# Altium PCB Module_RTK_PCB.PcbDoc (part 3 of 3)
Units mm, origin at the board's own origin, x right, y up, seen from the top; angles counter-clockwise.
Board outline 99.98 x 60 mm, 4 copper layers (Top Layer, gnd, vcc, Bottom Layer), stack 1.536 mm thick; 168 components, 121 nets, 582 pads, 666 vias.
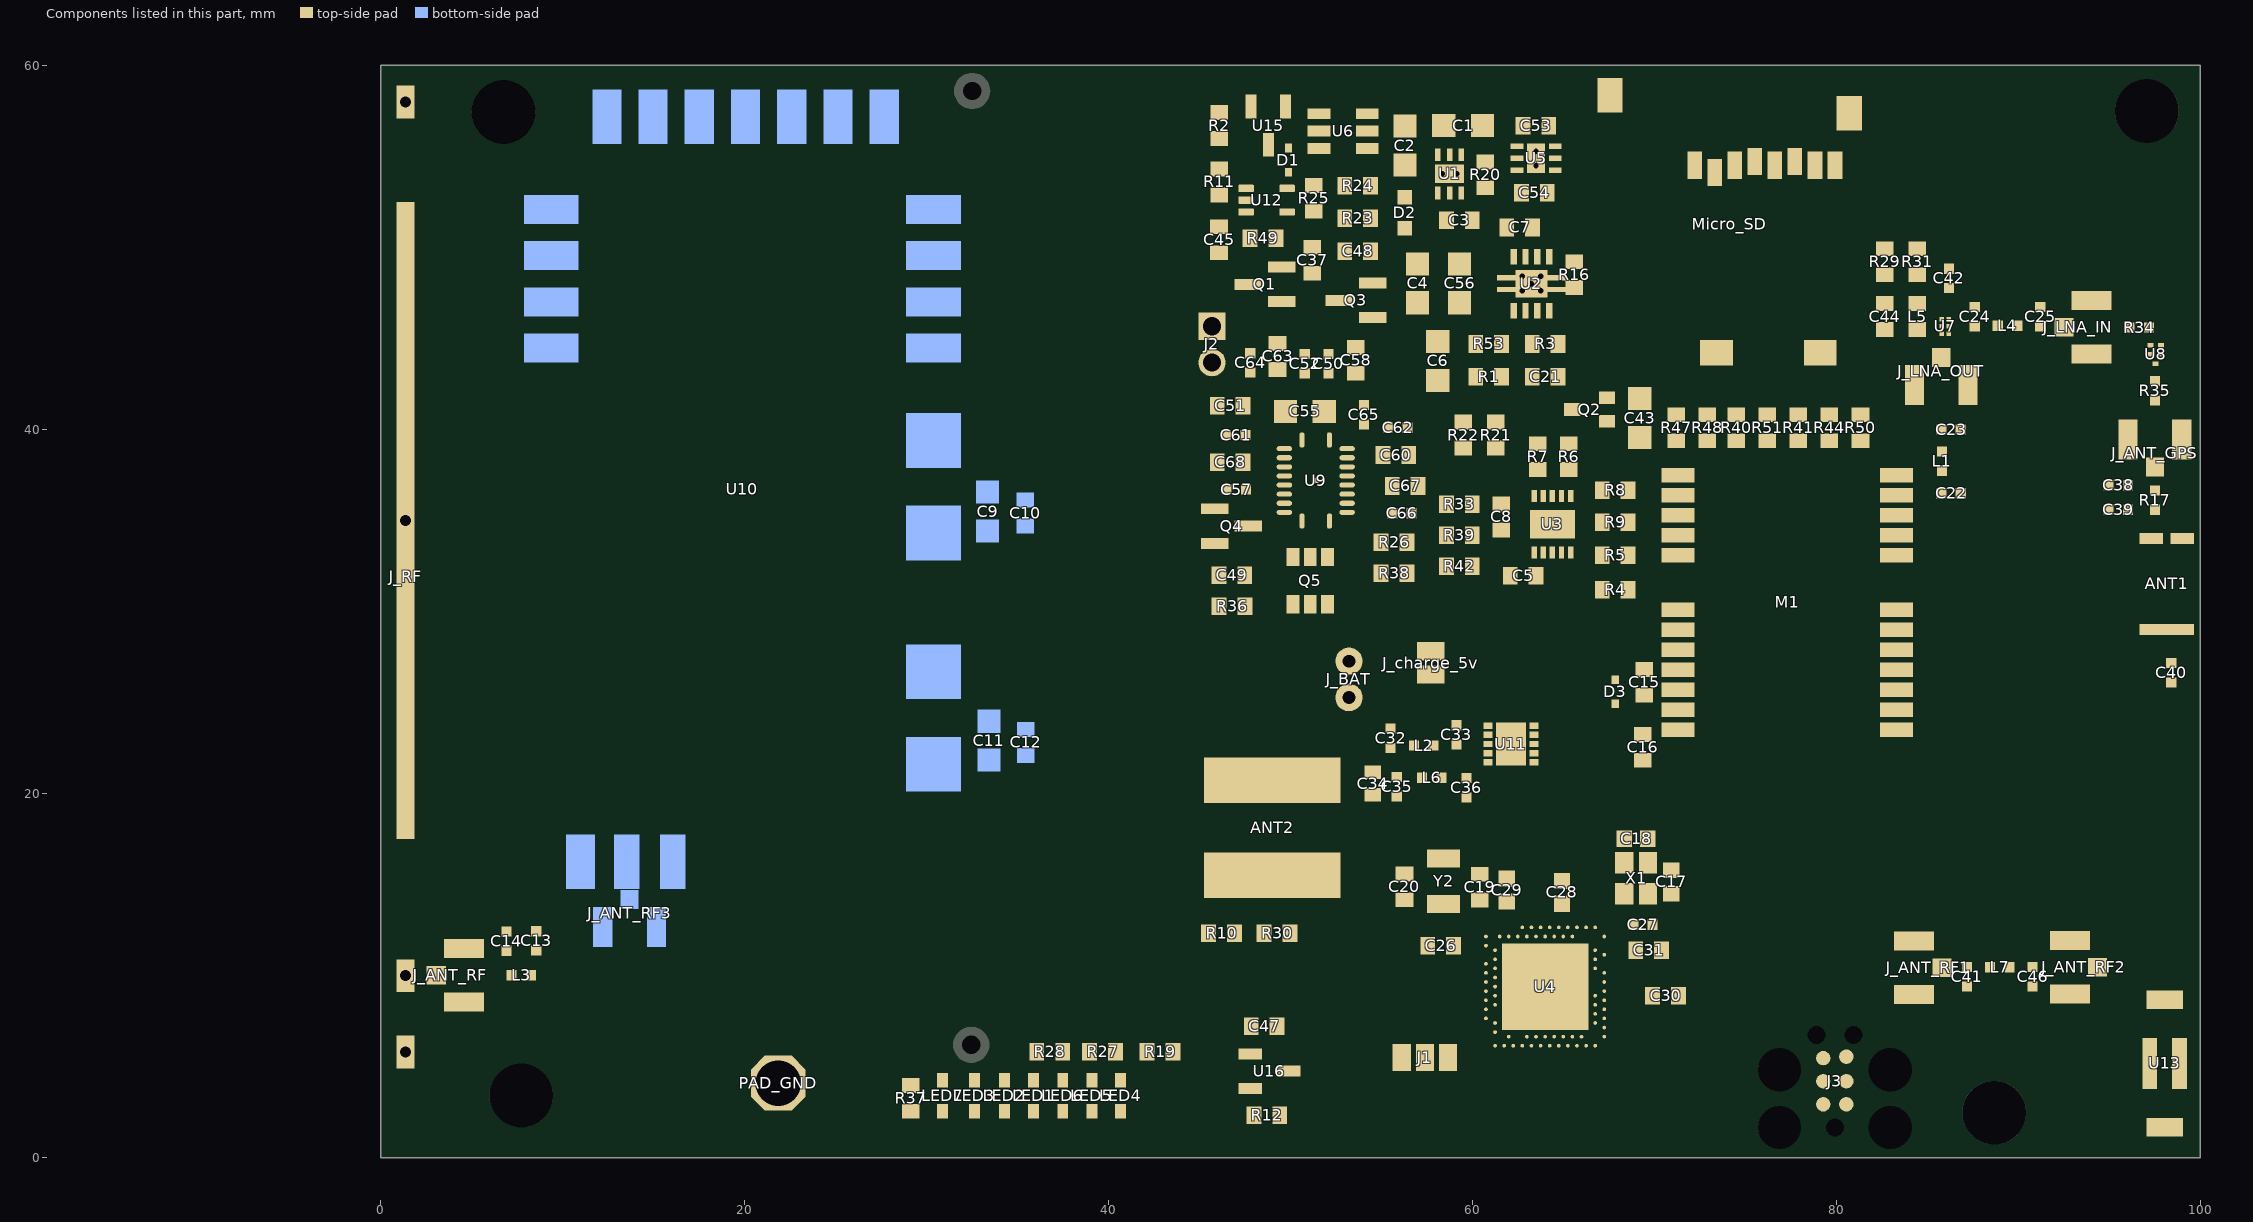
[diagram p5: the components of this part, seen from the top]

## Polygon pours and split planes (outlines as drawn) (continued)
VBAT on vcc "vcc-VBAT" (solid, pour order 23): 51.318,35.275 65.7,35.275 65.7,39.175 44.825,39.175 44.725,39.075 44.725,26.075 55.487,26.075 55.487,30.65 51.254,30.65
VCC_USB_ON on vcc "vcc-VCC_USB_ON" (solid, pour order 21): 51.678,34.8 65.7,34.8 65.7,31.05 51.678,31.05
VCC_PA on vcc "vcc-VCC_PA" (solid, pour order 25): 44.35,39.45 44.45,39.55 65.7,39.55 65.7,47.775 65.675,47.8 38.9,47.8 38.9,30.6 38.85,30.55 38.8,30.6 23.6,30.6 23.6,15.225 23.575,15.2 23.7,15.075 44.425,15.075
VCC on vcc "vcc-VCC" (solid, pour order 27): 66.875,26.375 66.85,26.35 66.85,23.325 71.4,23.325 71.475,23.4 71.475,30.678 55.85,30.678 55.85,25.7 44.75,25.7 44.75,14.75 44.725,14.725 23.25,14.725 23.25,30.9 23.225,30.925 38.475,30.925 38.525,30.975 38.525,48.175 55.425,48.175 55.45,48.15 55.45,51.025 58.6,51.025 58.6,54.677 53.998,54.677 53.975,54.7 54,54.725 54,59.95 0,59.95 0,0 55.575,0 55.6,0.025 55.6,14.075 58.6,14.075 58.689,14.164 58.689,26.437
GND on gnd "gnd-No Net" (solid, pour order 19): 0,0 0,60 99.975,60 99.975,0
GND on Top Layer "Top Layer-No Net" (solid, pour order 33): 0,60.025 99.975,60.025 99.975,0.025 99.95,0 0,0
GND on Bottom Layer "Bottom Layer-GND" (solid, pour order 35): 0,60 99.975,60 99.975,0 0,0

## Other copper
Top Layer:
  pour cut-out: 94.1,34.475 99.975,34.475 99.975,27.7 96,27.7 96,28.55 94.075,28.55 94.075,34.45
  pour cut-out: 95,10.2 99.975,10.2 99.975,0 94.975,0
gnd:
  pour cut-out: 94.1,34.475 99.975,34.475 99.975,27.725 99.95,27.7 96,27.7 96,28.55 95.95,28.6 94.075,28.6
  pour cut-out: 95,10.2 99.975,10.2 99.95,10.175 99.95,-0.025 95,-0.025 94.975,0
vcc:
  pour cut-out: 95,10.2 99.975,10.2 99.975,0 99.95,-0.025 99.925,0 94.975,0
  pour cut-out: 94.1,34.475 99.975,34.475 99.975,27.7 96,27.7 96,28.55 94.125,28.55 94.075,28.6
  pour cut-out: 51.318,35.275
Bottom Layer:
  pour cut-out: 94.1,34.475 99.975,34.475 99.975,27.725 99.95,27.7 96,27.7 96,28.55 95.95,28.6 94.075,28.6
  pour cut-out: 99.975,10.2 95,10.2 94.975,10.175 94.975,0 99.925,0 99.95,-0.025
  pour cut-out: 99.975,0

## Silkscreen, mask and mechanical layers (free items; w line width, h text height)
Top Overlay:
  lines w0.254: 10.06,7.5 44.06,7.5 44.06,57.5 10.06,57.5 10.06,7.5
  text "fix bat" at 34,58.393 h0.6
  text "fix bat" at 27.45,6.45 h0.6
